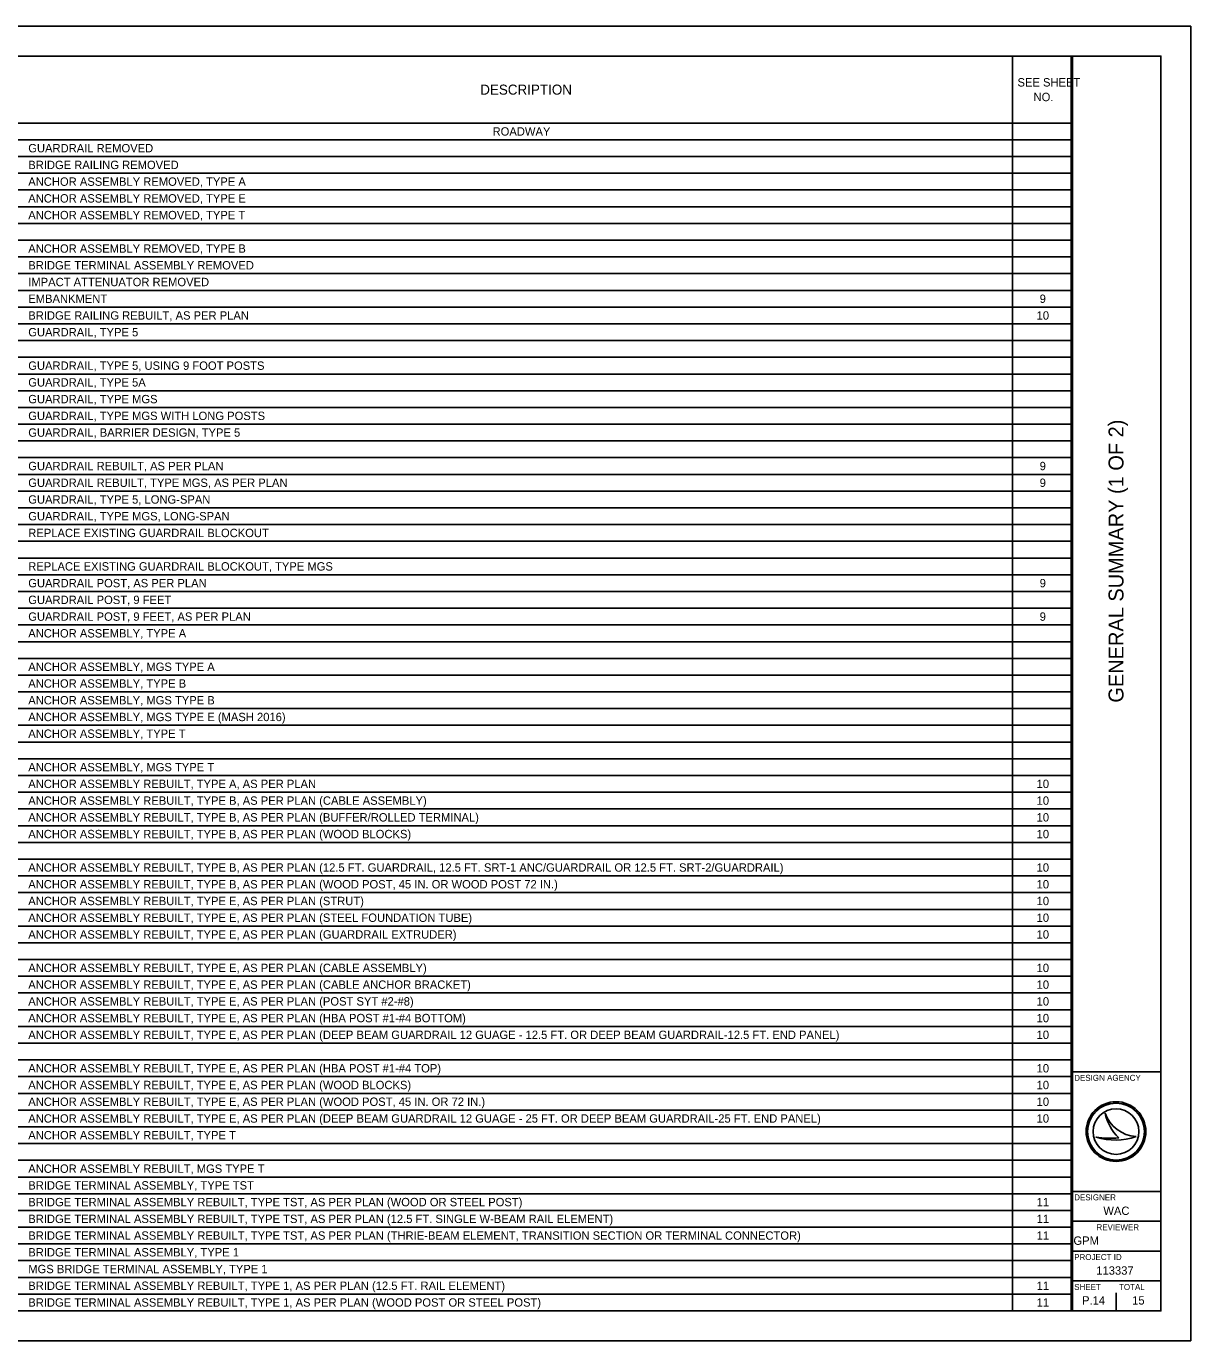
# Model space of a CAD drawing. Extents: x 0 to 34, y 0 to 22.
# Drawn here: x 14.51 to 34, y 0 to 22 of the extents above; entities that cross this region are included whole.
import ezdxf

# ---------------------------------------------------------------- set-up
doc = ezdxf.new("R2010")
doc.units = 0
for name, color, linetype in [('Default', 7, 'Continuous'), ('SH_Border', 7, 'Continuous'), ('SH_Cut_Line', 7, 'Continuous'), ('SH_Data', 7, 'Continuous')]:
    doc.layers.add(name, color=color, linetype=linetype)

msp = doc.modelspace()

# ---------------------------------------------------------------- linework, layer by layer
at = {"layer": 'Default'}
for p, q in [((1.5, 21.5), (32.02, 21.5)), ((31.015, 21.5), (31.015, 0.5)), ((32.02, 21.5), (32.02, 0.5)), ((1.5, 20.38), (32.02, 20.38)), ((1.5, 20.1), (32.02, 20.1)), ((1.5, 19.82), (32.02, 19.82)), ((1.5, 19.54), (32.02, 19.54)), ((1.5, 19.26), (32.02, 19.26)), ((1.5, 18.98), (32.02, 18.98)), ((1.5, 18.7), (32.02, 18.7)), ((1.5, 18.42), (32.02, 18.42)), ((1.5, 18.14), (32.02, 18.14)), ((1.5, 17.86), (32.02, 17.86)), ((1.5, 17.58), (32.02, 17.58)), ((1.5, 17.3), (32.02, 17.3)), ((1.5, 17.02), (32.02, 17.02)), ((1.5, 16.74), (32.02, 16.74)), ((1.5, 16.46), (32.02, 16.46)), ((1.5, 16.18), (32.02, 16.18)), ((1.5, 15.9), (32.02, 15.9)), ((1.5, 15.62), (32.02, 15.62)), ((1.5, 15.34), (32.02, 15.34)), ((1.5, 15.06), (32.02, 15.06)), ((1.5, 14.78), (32.02, 14.78)), ((1.5, 14.5), (32.02, 14.5)), ((1.5, 14.22), (32.02, 14.22)), ((1.5, 13.94), (32.02, 13.94)), ((1.5, 13.66), (32.02, 13.66)), ((1.5, 13.38), (32.02, 13.38)), ((1.5, 13.1), (32.02, 13.1)), ((1.5, 12.82), (32.02, 12.82)), ((1.5, 12.54), (32.02, 12.54)), ((1.5, 12.26), (32.02, 12.26)), ((1.5, 11.98), (32.02, 11.98)), ((1.5, 11.7), (32.02, 11.7)), ((1.5, 11.42), (32.02, 11.42)), ((1.5, 11.14), (32.02, 11.14)), ((1.5, 10.86), (32.02, 10.86)), ((1.5, 10.58), (32.02, 10.58)), ((1.5, 10.3), (32.02, 10.3)), ((1.5, 10.02), (32.02, 10.02)), ((1.5, 9.74), (32.02, 9.74)), ((1.5, 9.46), (32.02, 9.46)), ((1.5, 9.18), (32.02, 9.18)), ((1.5, 8.9), (32.02, 8.9)), ((1.5, 8.62), (32.02, 8.62)), ((1.5, 8.34), (32.02, 8.34)), ((1.5, 8.06), (32.02, 8.06)), ((1.5, 7.78), (32.02, 7.78)), ((1.5, 7.5), (32.02, 7.5)), ((1.5, 7.22), (32.02, 7.22)), ((1.5, 6.94), (32.02, 6.94)), ((1.5, 6.66), (32.02, 6.66)), ((1.5, 6.38), (32.02, 6.38)), ((1.5, 6.1), (32.02, 6.1)), ((1.5, 5.82), (32.02, 5.82)), ((1.5, 5.54), (32.02, 5.54)), ((1.5, 5.26), (32.02, 5.26)), ((1.5, 4.98), (32.02, 4.98)), ((1.5, 4.7), (32.02, 4.7)), ((1.5, 4.42), (32.02, 4.42)), ((1.5, 4.14), (32.02, 4.14)), ((1.5, 3.86), (32.02, 3.86)), ((1.5, 3.58), (32.02, 3.58)), ((1.5, 3.3), (32.02, 3.3)), ((1.5, 3.02), (32.02, 3.02)), ((1.5, 2.74), (32.02, 2.74)), ((1.5, 2.46), (32.02, 2.46)), ((1.5, 2.18), (32.02, 2.18)), ((1.5, 1.9), (32.02, 1.9)), ((1.5, 1.62), (32.02, 1.62)), ((1.5, 1.34), (32.02, 1.34)), ((1.5, 1.06), (32.02, 1.06)), ((1.5, 0.78), (32.02, 0.78)), ((1.5, 0.5), (32.02, 0.5))]:
    msp.add_line(p, q, dxfattribs=at)
at = {"layer": 'SH_Border'}
for p, q in [((32, 0.5), (32, 21.5)), ((32, 4.5), (33.5, 4.5)), ((32, 2.5), (33.5, 2.5)), ((32, 2), (33.5, 2)), ((32, 1.5), (33.5, 1.5)), ((32, 1), (33.5, 1))]:
    msp.add_line(p, q, dxfattribs=at)
msp.add_lwpolyline([(1.5, 21.5), (33.5, 21.5), (33.5, 0.5), (1.5, 0.5)], close=True, dxfattribs=at)
at = {"layer": 'SH_Cut_Line'}
msp.add_lwpolyline([(0, 0), (34, 0), (34, 22), (0, 22)], close=True, dxfattribs=at)
at = {"layer": 'SH_Data'}
for p, q in [((32.567, 3.81), (32.567, 3.81)), ((32.417, 3.41), (32.417, 3.41)), ((32.75, 3.5), (32.75, 3.5)), ((33.087, 3.419), (33.087, 3.419)), ((32.375, 0.675), (32.375, 0.675)), ((32.75, 0.5), (32.75, 0.8))]:
    msp.add_line(p, q, dxfattribs=at)
for radius in [0.5, 0.477, 0.477, 0.382]:
    msp.add_circle((32.75, 3.5), radius, dxfattribs=at)
for centre, radius, start, end in [((33.116, 3.998), 0.58, 198.9257, 198.9319), ((33.347, 3.97), 0.796, 191.6379, 191.6421), ((33.116, 3.998), 0.58, 198.9319, 267.1657), ((33.347, 3.97), 0.796, 191.6421, 226.0947), ((32.739, 4.37), 1.013, 251.4576, 290.0832), ((32.648, 4.654), 1.266, 259.4964, 259.4995), ((32.739, 4.37), 1.013, 251.4527, 251.4576), ((32.648, 4.654), 1.266, 259.4995, 276.6672)]:
    msp.add_arc(centre, radius, start, end, dxfattribs=at)

# ---------------------------------------------------------------- texts
at = {"layer": 'Default'}
for s, height, p in [('SEE SHEET ', 0.14, (31.101, 20.992)), ('DESCRIPTION', 0.168, (22.109, 20.856)), ('NO.', 0.14, (31.37, 20.747)), ('ROADWAY', 0.14, (22.316, 20.17)), ('GUARDRAIL REMOVED', 0.14, (14.545, 19.89)), ('BRIDGE RAILING REMOVED', 0.14, (14.545, 19.61)), ('ANCHOR ASSEMBLY REMOVED, TYPE A', 0.14, (14.545, 19.33)), ('ANCHOR ASSEMBLY REMOVED, TYPE E', 0.14, (14.545, 19.05)), ('ANCHOR ASSEMBLY REMOVED, TYPE T', 0.14, (14.545, 18.77)), ('ANCHOR ASSEMBLY REMOVED, TYPE B', 0.14, (14.545, 18.21)), ('BRIDGE TERMINAL ASSEMBLY REMOVED', 0.14, (14.545, 17.93)), ('IMPACT ATTENUATOR REMOVED', 0.14, (14.545, 17.65)), ('EMBANKMENT', 0.14, (14.545, 17.37)), ('9', 0.14, (31.472, 17.37)), ('BRIDGE RAILING REBUILT, AS PER PLAN', 0.14, (14.545, 17.09)), ('10', 0.14, (31.421, 17.09)), ('GUARDRAIL, TYPE 5', 0.14, (14.545, 16.81)), ('GUARDRAIL, TYPE 5, USING 9 FOOT POSTS', 0.14, (14.545, 16.25)), ('GUARDRAIL, TYPE 5A', 0.14, (14.545, 15.97)), ('GUARDRAIL, TYPE MGS', 0.14, (14.545, 15.69)), ('GUARDRAIL, TYPE MGS WITH LONG POSTS', 0.14, (14.545, 15.41)), ('GUARDRAIL, BARRIER DESIGN, TYPE 5', 0.14, (14.545, 15.13)), ('GUARDRAIL REBUILT, AS PER PLAN', 0.14, (14.545, 14.57)), ('9', 0.14, (31.472, 14.57)), ('GUARDRAIL REBUILT, TYPE MGS, AS PER PLAN', 0.14, (14.545, 14.29)), ('9', 0.14, (31.472, 14.29)), ('GUARDRAIL, TYPE 5, LONG-SPAN', 0.14, (14.545, 14.01)), ('GUARDRAIL, TYPE MGS, LONG-SPAN', 0.14, (14.545, 13.73)), ('REPLACE EXISTING GUARDRAIL BLOCKOUT', 0.14, (14.545, 13.45)), ('REPLACE EXISTING GUARDRAIL BLOCKOUT, TYPE MGS', 0.14, (14.545, 12.89)), ('GUARDRAIL POST, AS PER PLAN', 0.14, (14.545, 12.61)), ('9', 0.14, (31.472, 12.61)), ('GUARDRAIL POST, 9 FEET', 0.14, (14.545, 12.33)), ('GUARDRAIL POST, 9 FEET, AS PER PLAN', 0.14, (14.545, 12.05)), ('9', 0.14, (31.472, 12.05)), ('ANCHOR ASSEMBLY, TYPE A', 0.14, (14.545, 11.77)), ('ANCHOR ASSEMBLY, MGS TYPE A', 0.14, (14.545, 11.21)), ('ANCHOR ASSEMBLY, TYPE B', 0.14, (14.545, 10.93)), ('ANCHOR ASSEMBLY, MGS TYPE B', 0.14, (14.545, 10.65)), ('ANCHOR ASSEMBLY, MGS TYPE E (MASH 2016)', 0.14, (14.545, 10.37)), ('ANCHOR ASSEMBLY, TYPE T', 0.14, (14.545, 10.09)), ('ANCHOR ASSEMBLY, MGS TYPE T', 0.14, (14.545, 9.53)), ('ANCHOR ASSEMBLY REBUILT, TYPE A, AS PER PLAN', 0.14, (14.545, 9.25)), ('10', 0.14, (31.421, 9.25)), ('ANCHOR ASSEMBLY REBUILT, TYPE B, AS PER PLAN (CABLE ASSEMBLY)', 0.14, (14.545, 8.97)), ('10', 0.14, (31.421, 8.97)), ('ANCHOR ASSEMBLY REBUILT, TYPE B, AS PER PLAN (BUFFER/ROLLED TERMINAL)', 0.14, (14.545, 8.69)), ('10', 0.14, (31.421, 8.69)), ('ANCHOR ASSEMBLY REBUILT, TYPE B, AS PER PLAN (WOOD BLOCKS)', 0.14, (14.545, 8.41)), ('10', 0.14, (31.421, 8.41)), ('ANCHOR ASSEMBLY REBUILT, TYPE B, AS PER PLAN (12.5 FT. GUARDRAIL, 12.5 FT. SRT-1 ANC/GUARDRAIL OR 12.5 FT. SRT-2/GUARDRAIL)', 0.14, (14.545, 7.85)), ('10', 0.14, (31.421, 7.85)), ('ANCHOR ASSEMBLY REBUILT, TYPE B, AS PER PLAN (WOOD POST, 45 IN. OR WOOD POST 72 IN.)', 0.14, (14.545, 7.57)), ('10', 0.14, (31.421, 7.57)), ('ANCHOR ASSEMBLY REBUILT, TYPE E, AS PER PLAN (STRUT)', 0.14, (14.545, 7.29)), ('10', 0.14, (31.421, 7.29)), ('ANCHOR ASSEMBLY REBUILT, TYPE E, AS PER PLAN (STEEL FOUNDATION TUBE)', 0.14, (14.545, 7.01)), ('10', 0.14, (31.421, 7.01)), ('ANCHOR ASSEMBLY REBUILT, TYPE E, AS PER PLAN (GUARDRAIL EXTRUDER)', 0.14, (14.545, 6.73)), ('10', 0.14, (31.421, 6.73)), ('ANCHOR ASSEMBLY REBUILT, TYPE E, AS PER PLAN (CABLE ASSEMBLY)', 0.14, (14.545, 6.17)), ('10', 0.14, (31.421, 6.17)), ('ANCHOR ASSEMBLY REBUILT, TYPE E, AS PER PLAN (CABLE ANCHOR BRACKET)', 0.14, (14.545, 5.89)), ('10', 0.14, (31.421, 5.89)), ('ANCHOR ASSEMBLY REBUILT, TYPE E, AS PER PLAN (POST SYT #2-#8)', 0.14, (14.545, 5.61)), ('10', 0.14, (31.421, 5.61)), ('ANCHOR ASSEMBLY REBUILT, TYPE E, AS PER PLAN (HBA POST #1-#4 BOTTOM)', 0.14, (14.545, 5.33)), ('10', 0.14, (31.421, 5.33)), ('ANCHOR ASSEMBLY REBUILT, TYPE E, AS PER PLAN (DEEP BEAM GUARDRAIL 12 GUAGE - 12.5 FT. OR DEEP BEAM GUARDRAIL-12.5 FT. END PANEL)', 0.14, (14.545, 5.05)), ('10', 0.14, (31.421, 5.05)), ('ANCHOR ASSEMBLY REBUILT, TYPE E, AS PER PLAN (HBA POST #1-#4 TOP)', 0.14, (14.545, 4.49)), ('10', 0.14, (31.421, 4.49)), ('ANCHOR ASSEMBLY REBUILT, TYPE E, AS PER PLAN (WOOD BLOCKS)', 0.14, (14.545, 4.21)), ('10', 0.14, (31.421, 4.21)), ('ANCHOR ASSEMBLY REBUILT, TYPE E, AS PER PLAN (WOOD POST, 45 IN. OR 72 IN.)', 0.14, (14.545, 3.93)), ('10', 0.14, (31.421, 3.93)), ('ANCHOR ASSEMBLY REBUILT, TYPE E, AS PER PLAN (DEEP BEAM GUARDRAIL 12 GUAGE - 25 FT. OR DEEP BEAM GUARDRAIL-25 FT. END PANEL)', 0.14, (14.545, 3.65)), ('10', 0.14, (31.421, 3.65)), ('ANCHOR ASSEMBLY REBUILT, TYPE T', 0.14, (14.545, 3.37)), ('ANCHOR ASSEMBLY REBUILT, MGS TYPE T', 0.14, (14.545, 2.81)), ('BRIDGE TERMINAL ASSEMBLY, TYPE TST', 0.14, (14.545, 2.53)), ('BRIDGE TERMINAL ASSEMBLY REBUILT, TYPE TST, AS PER PLAN (WOOD OR STEEL POST)', 0.14, (14.545, 2.25)), ('11', 0.14, (31.422, 2.25)), ('BRIDGE TERMINAL ASSEMBLY REBUILT, TYPE TST, AS PER PLAN (12.5 FT. SINGLE W-BEAM RAIL ELEMENT)', 0.14, (14.545, 1.97)), ('11', 0.14, (31.422, 1.97)), ('BRIDGE TERMINAL ASSEMBLY REBUILT, TYPE TST, AS PER PLAN (THRIE-BEAM ELEMENT, TRANSITION SECTION OR TERMINAL CONNECTOR)', 0.14, (14.545, 1.69)), ('11', 0.14, (31.422, 1.69)), ('BRIDGE TERMINAL ASSEMBLY, TYPE 1', 0.14, (14.545, 1.41)), ('MGS BRIDGE TERMINAL ASSEMBLY, TYPE 1', 0.14, (14.545, 1.13)), ('BRIDGE TERMINAL ASSEMBLY REBUILT, TYPE 1, AS PER PLAN (12.5 FT. RAIL ELEMENT)', 0.14, (14.545, 0.85)), ('11', 0.14, (31.422, 0.85)), ('BRIDGE TERMINAL ASSEMBLY REBUILT, TYPE 1, AS PER PLAN (WOOD POST OR STEEL POST)', 0.14, (14.545, 0.57)), ('11', 0.14, (31.422, 0.57))]:
    msp.add_text(s, height=height, dxfattribs=at).set_placement(p)
at = {"layer": 'SH_Data'}
msp.add_text('GENERAL SUMMARY (1 OF 2)', height=0.25, rotation=90, dxfattribs=at).set_placement((32.875, 10.68))
for s, height, p in [('DESIGN AGENCY', 0.1, (32.05, 4.35)), ('DESIGNER', 0.1, (32.05, 2.35)), ('WAC', 0.14, (32.538, 2.105)), ('REVIEWER', 0.1, (32.422, 1.85)), ('GPM', 0.14, (32.038, 1.605)), ('PROJECT ID', 0.1, (32.05, 1.35)), ('113337', 0.14, (32.42, 1.105)), ('SHEET', 0.1, (32.05, 0.85)), ('TOTAL', 0.1, (32.8, 0.85)), ('P.14', 0.14, (32.182, 0.605)), ('15', 0.14, (33.02, 0.605))]:
    msp.add_text(s, height=height, dxfattribs=at).set_placement(p)

doc.saveas('drawing.dxf')
